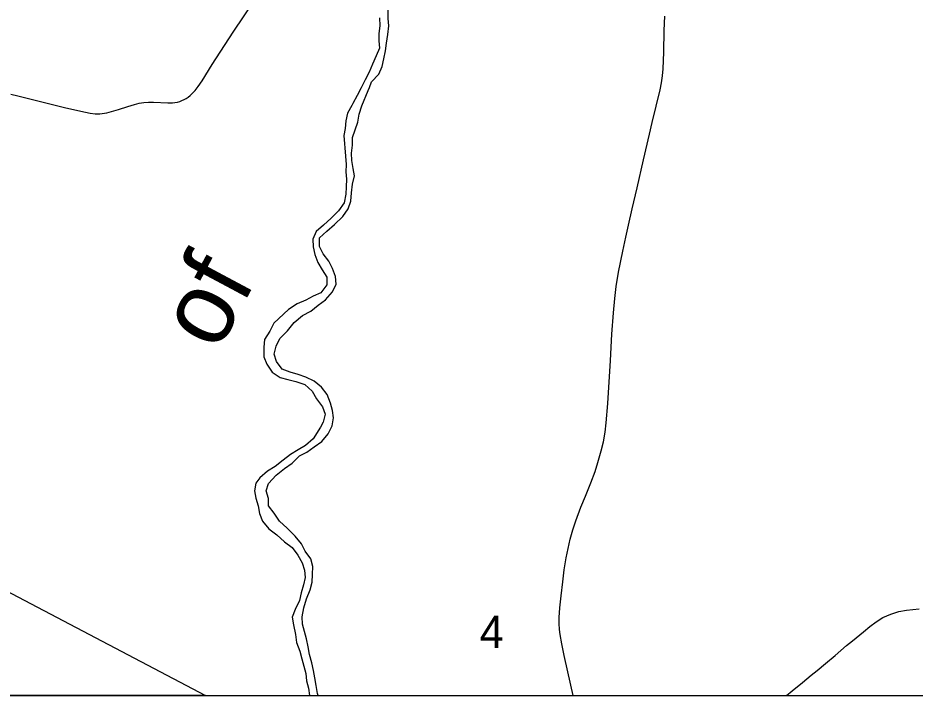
# Model space of a CAD drawing. Extents: x -7.5 to 53.5, y 0 to 22.
# Drawn here: x 6.583 to 7.745, y 16.725 to 17.62 of the extents above; entities that cross this region are included whole.
import ezdxf

# ---------------------------------------------------------------- set-up
doc = ezdxf.new("R2010")
doc.units = 0
for name, color, linetype in [('GM_X_County_Road', 7, 'Continuous'), ('GM_X_Major_River', 7, 'Continuous'), ('GM_X_Major_River_Text', 7, 'Continuous'), ('GM_X_Section_Text', 7, 'Continuous'), ('GM_X_Township_Road', 7, 'Continuous'), ('SH_Text', 7, 'Continuous')]:
    doc.layers.add(name, color=color, linetype=linetype)

msp = doc.modelspace()

# ---------------------------------------------------------------- linework, layer by layer
at = {"layer": 'GM_X_County_Road'}
for points in [[(6.5742, 17.5209), (6.5832, 17.5188), (6.6073, 17.5128), (6.6435, 17.5037), (6.6647, 17.4987), (6.6769, 17.4962), (6.683, 17.4955), (6.6892, 17.4955), (6.6923, 17.4957), (6.6984, 17.4967), (6.7045, 17.4982), (6.7135, 17.5008), (6.7253, 17.5047), (6.7341, 17.5075), (6.7401, 17.5091), (6.7462, 17.5101), (6.7524, 17.5106), (6.7586, 17.5107), (6.7772, 17.5098), (6.7834, 17.5098), (6.7865, 17.5101), (6.7896, 17.5107), (6.7926, 17.5115), (6.7955, 17.5126), (6.7983, 17.5139), (6.801, 17.5154), (6.8036, 17.5171), (6.806, 17.519), (6.8084, 17.5211), (6.8105, 17.5233), (6.8126, 17.5256), (6.8164, 17.5306), (6.8216, 17.5383), (6.8348, 17.5594), (6.8618, 17.6011), (6.8911, 17.6452)], [(7.3019, 16.7419), (7.2952, 16.7724), (7.2905, 16.7936), (7.2873, 16.8088), (7.2852, 16.821), (7.2844, 16.8272), (7.2838, 16.835), (7.284, 16.8428), (7.2848, 16.8552), (7.2863, 16.8707), (7.2884, 16.8892), (7.2904, 16.9046), (7.2929, 16.92), (7.2953, 16.9322), (7.2982, 16.9443), (7.3016, 16.9563), (7.3055, 16.9682), (7.3121, 16.9857), (7.3179, 17), (7.3249, 17.0173), (7.3303, 17.0319), (7.3341, 17.0436), (7.3383, 17.0586), (7.3411, 17.0706), (7.3433, 17.0828), (7.3448, 17.0951), (7.3467, 17.1199), (7.3501, 17.1757), (7.3522, 17.2098), (7.3542, 17.2377), (7.3559, 17.2563), (7.3578, 17.2717), (7.3608, 17.2901), (7.3662, 17.3176), (7.37, 17.3358), (7.3735, 17.351), (7.3783, 17.3722), (7.3847, 17.3994), (7.3931, 17.4357), (7.4007, 17.4691), (7.4043, 17.4842), (7.4146, 17.5264), (7.4165, 17.5354), (7.4178, 17.5446), (7.4185, 17.5538), (7.4192, 17.5755), (7.42, 17.6034), (7.4206, 17.622)]]:
    msp.add_lwpolyline(points, dxfattribs=at)
at = {"layer": 'GM_X_Major_River'}
for points in [[(7.0407, 17.5368), (7.0502, 17.5466), (7.0548, 17.5568), (7.0568, 17.5666), (7.0592, 17.5772), (7.0604, 17.5871), (7.062, 17.5981), (7.0632, 17.6094), (7.0625, 17.6189), (7.0623, 17.6292), (7.0608, 17.6387), (7.0609, 17.6493), (7.0602, 17.6588), (7.0595, 17.6686), (7.0596, 17.6781), (7.0601, 17.6876), (7.0609, 17.6982), (7.0606, 17.7081), (7.0622, 17.7179), (7.0676, 17.7281), (7.0703, 17.7315)], [(7.0512, 17.6198), (7.0519, 17.6095), (7.0506, 17.5993), (7.0506, 17.5898), (7.0512, 17.5803), (7.047, 17.5705), (7.0423, 17.5596), (7.0381, 17.5494), (7.0327, 17.5396), (7.0277, 17.529), (7.0223, 17.5192), (7.0167, 17.5089)], [(7.0366, 17.5255), (7.0383, 17.5296), (7.0407, 17.5368)], [(6.9717, 16.7419), (6.9712, 16.7445), (6.9694, 16.7548), (6.9675, 16.7646), (6.9657, 16.7741), (6.9635, 16.784), (6.9606, 16.7947), (6.9588, 16.8049), (6.9566, 16.8152), (6.954, 16.8247), (6.9518, 16.8342), (6.9511, 16.8437), (6.9531, 16.8554), (6.9566, 16.8668), (6.9613, 16.8785), (6.964, 16.8887), (6.9645, 16.8985), (6.9649, 16.9088), (6.9624, 16.9187), (6.9549, 16.9286), (6.9504, 16.9381), (6.9421, 16.948), (6.9316, 16.9584), (6.9218, 16.9676), (6.9147, 16.9779), (6.9076, 16.9874), (6.9077, 16.9969), (6.9047, 17.0068), (6.9075, 17.0166), (6.9174, 17.0271), (6.9285, 17.0358), (6.938, 17.0429), (6.9476, 17.0523), (6.9571, 17.0571), (6.9666, 17.0639), (6.9765, 17.071), (6.9849, 17.0808), (6.99, 17.0913), (6.9916, 17.1016), (6.9905, 17.111), (6.9879, 17.1205), (6.9835, 17.1316), (6.9763, 17.1411), (6.9666, 17.1492), (6.956, 17.1542), (6.9458, 17.1577), (6.9356, 17.1608), (6.9254, 17.1647), (6.9179, 17.1747), (6.9149, 17.1842), (6.9177, 17.1944), (6.9223, 17.2042), (6.9322, 17.2143), (6.941, 17.2249), (6.9517, 17.2339), (6.9624, 17.2395), (6.9719, 17.2474), (6.9814, 17.2545), (6.9906, 17.2646), (6.9953, 17.2748), (6.9942, 17.2847), (6.9905, 17.295), (6.9857, 17.3045), (6.9782, 17.314), (6.9737, 17.3236), (6.9738, 17.3346), (6.9833, 17.3432), (6.9932, 17.3522), (7.0036, 17.3623), (7.0105, 17.3725), (7.0143, 17.3823), (7.0152, 17.393), (7.0164, 17.4043), (7.0188, 17.4149), (7.017, 17.4244), (7.0155, 17.4351), (7.0152, 17.4445), (7.0165, 17.4548), (7.0162, 17.4646), (7.0197, 17.4748), (7.0232, 17.4847), (7.0251, 17.4949), (7.0283, 17.5058), (7.0366, 17.5255)], [(7.0167, 17.5089), (7.0154, 17.506), (7.01, 17.4962), (7.0076, 17.4863), (7.0068, 17.4765), (7.0051, 17.4673)], [(7.0051, 17.4673), (7.0072, 17.4404), (7.0083, 17.4298), (7.0078, 17.4203), (7.0085, 17.4108), (7.0081, 17.4006), (7.0076, 17.3911), (7.0056, 17.3802), (6.9983, 17.3696), (6.9888, 17.3602), (6.9788, 17.3512), (6.9693, 17.3429), (6.965, 17.3331), (6.9653, 17.3229), (6.9675, 17.313), (6.9716, 17.3027), (6.9772, 17.2932), (6.9832, 17.2837), (6.9831, 17.2738), (6.9755, 17.2636), (6.9656, 17.2592), (6.9557, 17.2539), (6.9446, 17.2491), (6.9336, 17.242), (6.9145, 17.224), (6.9091, 17.2138), (6.9026, 17.2032), (6.9017, 17.193), (6.9016, 17.1805), (6.9053, 17.171), (6.9124, 17.1607), (6.9226, 17.1537), (6.9328, 17.151), (6.943, 17.1486), (6.9544, 17.1447), (6.9642, 17.1359), (6.9698, 17.126), (6.9776, 17.1157), (6.981, 17.1062), (6.9782, 17.096), (6.975, 17.0895)], [(6.975, 17.0895), (6.9655, 17.0741), (6.9556, 17.0655), (6.9461, 17.0602), (6.9362, 17.0539), (6.9267, 17.0468), (6.9164, 17.0385), (6.9061, 17.0326), (6.8963, 17.0238)], [(6.8963, 17.0238), (6.8912, 17.0168), (6.8896, 17.0069), (6.891, 16.9974), (6.894, 16.9875), (6.8961, 16.9777), (6.8999, 16.9678), (6.9081, 16.9578), (6.9183, 16.9501), (6.9284, 16.941), (6.9382, 16.9337), (6.9454, 16.9237), (6.9513, 16.9138), (6.9543, 16.9043), (6.955, 16.8948), (6.953, 16.885), (6.9499, 16.8748), (6.9475, 16.8649), (6.9421, 16.8532), (6.9382, 16.8434), (6.9401, 16.8332), (6.9426, 16.8206), (6.944, 16.8104), (6.9481, 16.7993), (6.9507, 16.7894), (6.9558, 16.7704), (6.9569, 16.7606), (6.9595, 16.7511), (6.9608, 16.7419)]]:
    msp.add_lwpolyline(points, dxfattribs=at)
at = {"layer": 'GM_X_Township_Road'}
msp.add_lwpolyline([(7.5783, 16.7419), (7.5857, 16.748), (7.599, 16.7588), (7.6103, 16.7681), (7.6178, 16.7742), (7.6286, 16.7833), (7.641, 16.7937), (7.656, 16.8064), (7.6634, 16.8126), (7.6778, 16.8244), (7.6861, 16.831), (7.6942, 16.8371), (7.703, 16.8426), (7.7131, 16.8472), (7.7236, 16.8504), (7.7336, 16.8524), (7.7501, 16.8542)], dxfattribs=at)
at = {"layer": 'SH_Text'}
for points in [[(6.8259, 16.7419), (6.5259, 16.7419), (5.2686, 17.561)], [(6.5259, 16.7419), (8.061, 16.7419), (8.061, 16.1744), (6.5259, 16.1744)]]:
    msp.add_lwpolyline(points, close=True, dxfattribs=at)

# ---------------------------------------------------------------- texts
at = {"layer": 'GM_X_Major_River_Text'}
msp.add_text('of', height=0.09472, rotation=61.8714, dxfattribs=at).set_placement((6.8416, 17.1854))
at = {"layer": 'GM_X_Section_Text'}
msp.add_text('4', height=0.0419, rotation=0, dxfattribs=at).set_placement((7.1809, 16.8033))

doc.saveas('drawing.dxf')
